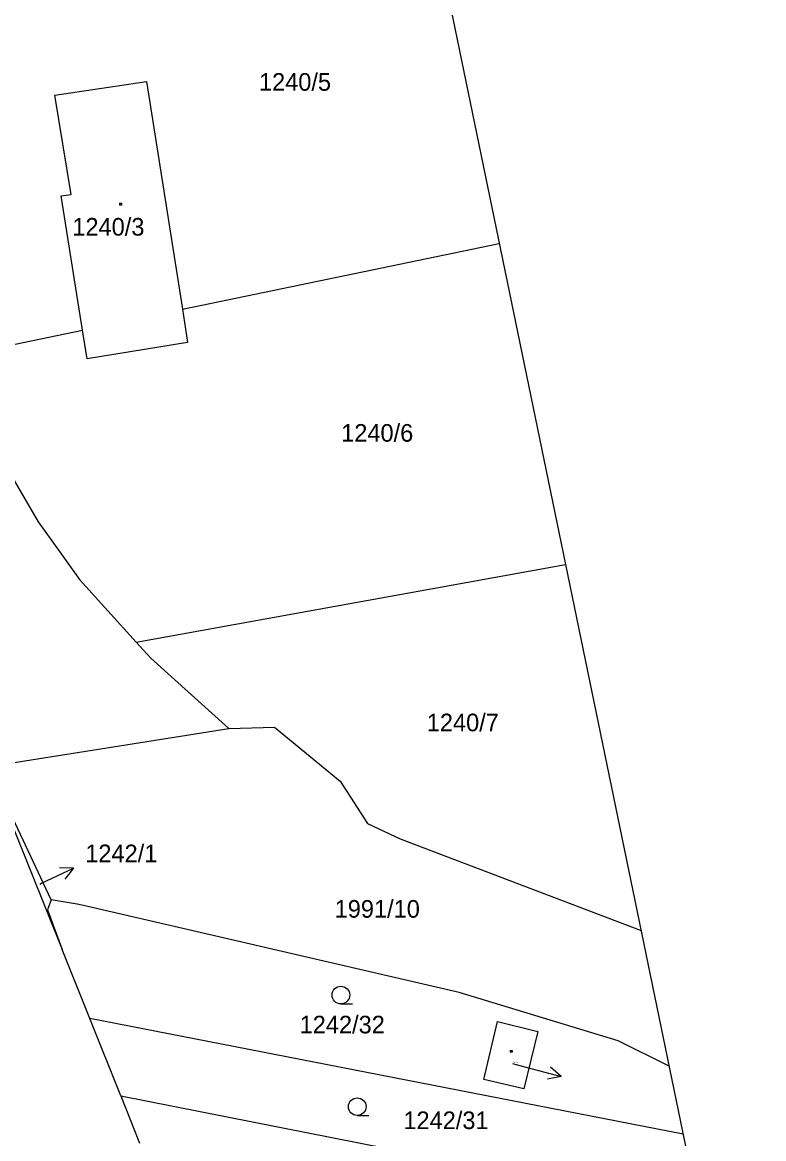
# Model space of a CAD drawing. Extents: x -804166 to -803706, y -1151030 to -1150147.
# Drawn here: x -803853.6 to -803790.5, y -1150525.9 to -1150430.9 of the extents above; entities that cross this region are included whole.
import ezdxf

# ---------------------------------------------------------------- set-up
doc = ezdxf.new("R2010")
doc.units = 0
for name, color, linetype in [('Default', 7, 'Continuous'), ('formát', 7, 'Continuous'), ('kn_celek - Cisla parcel pomocna', 7, 'Continuous'), ('kn_celek - Cisla pozemkovych parcel', 7, 'Continuous'), ('kn_celek - Cisla stavebnich parcel', 7, 'Continuous'), ('kn_celek - Hranice parcel', 7, 'Continuous'), ('kn_celek - Znacky budov', 7, 'Continuous'), ('kn_celek - Znacky kultur', 7, 'Continuous')]:
    doc.layers.add(name, color=color, linetype=linetype)

# ---------------------------------------------------------------- blocks, each defined once
blk = doc.blocks.new('304')
at = {"layer": 'Default'}
blk.add_line((-0.07, 0), (9.85, 0), dxfattribs=at)
blk.add_circle((-0.08, 7.5), 7.5, dxfattribs=at)
blk = doc.blocks.new('402')
at = {"layer": 'Default'}
for p, q in [((-0.77, 0.75), (0.73, 0.75)), ((-0.77, 0.75), (-0.77, -0.75)), ((0.73, 0.75), (0.73, -0.75)), ((0.73, -0.75), (-0.77, -0.75))]:
    blk.add_line(p, q, dxfattribs=at)
blk = doc.blocks.new('Z61')
at = {"layer": 'Default'}
for p, q in [((0, 0), (30, 0)), ((30, 0), (19.21, 5.26)), ((30, 0), (19.21, -5.26))]:
    blk.add_line(p, q, dxfattribs=at)

msp = doc.modelspace()

# ---------------------------------------------------------------- linework, layer by layer
at = {"layer": 'formát'}
msp.add_line((-803832.972, -1150353.011), (-803790.512, -1150558.674), dxfattribs=at)
at = {"layer": 'kn_celek - Cisla parcel pomocna'}
for p, q in [((-803852.112, -1150504.197), (-803851.95, -1150504.12)), ((-803811.889, -1150519.448), (-803810.63, -1150519.79))]:
    msp.add_line(p, q, dxfattribs=at)
at = {"layer": 'kn_celek - Hranice parcel'}
for p, q in [((-803850.83, -1150437.12), (-803843.02, -1150435.94)), ((-803843.02, -1150435.94), (-803839.97, -1150455.32)), ((-803849.45, -1150445.54), (-803850.83, -1150437.12)), ((-803850.28, -1150445.67), (-803849.45, -1150445.54)), ((-803848.47, -1150457.09), (-803850.28, -1150445.67)), ((-803839.97, -1150455.32), (-803813.008, -1150449.711)), ((-803839.97, -1150455.32), (-803839.53, -1150458.14)), ((-803859.37, -1150459.36), (-803848.47, -1150457.09)), ((-803848.09, -1150459.52), (-803848.47, -1150457.09)), ((-803839.53, -1150458.14), (-803848.09, -1150459.52)), ((-803855.19, -1150468.33), (-803852.25, -1150473.4)), ((-803852.25, -1150473.4), (-803850.44, -1150475.92)), ((-803850.44, -1150475.92), (-803848.74, -1150478.29)), ((-803843.91, -1150483.63), (-803807.372, -1150477.008)), ((-803848.74, -1150478.29), (-803843.91, -1150483.63)), ((-803843.91, -1150483.63), (-803842.67, -1150485)), ((-803842.67, -1150485), (-803836.01, -1150490.97)), ((-803856.47, -1150494.21), (-803836.01, -1150490.97)), ((-803836.01, -1150490.97), (-803832.13, -1150490.85)), ((-803832.13, -1150490.85), (-803826.54, -1150495.44)), ((-803851.14, -1150505.55), (-803856.47, -1150494.21)), ((-803856.47, -1150494.21), (-803850.2, -1150509.77)), ((-803826.54, -1150495.44), (-803824.23, -1150499.05)), ((-803824.23, -1150499.05), (-803821.45, -1150500.35)), ((-803821.45, -1150500.35), (-803800.942, -1150508.154)), ((-803851.14, -1150505.55), (-803851.46, -1150506.38)), ((-803848.93, -1150505.9), (-803851.14, -1150505.55)), ((-803848.39, -1150506.03), (-803848.93, -1150505.9)), ((-803816.42, -1150513.42), (-803848.39, -1150506.03)), ((-803851.46, -1150506.38), (-803850.2, -1150509.77)), ((-803847.85, -1150515.64), (-803850.2, -1150509.77)), ((-803802.9, -1150517.53), (-803816.42, -1150513.42)), ((-803845.22, -1150522.21), (-803847.85, -1150515.64)), ((-803797.366, -1150525.476), (-803847.85, -1150515.64)), ((-803814.33, -1150520.81), (-803813.17, -1150515.89)), ((-803813.17, -1150515.89), (-803809.73, -1150516.73)), ((-803809.73, -1150516.73), (-803810.93, -1150521.61)), ((-803798.563, -1150519.677), (-803802.9, -1150517.53)), ((-803810.93, -1150521.61), (-803814.33, -1150520.81)), ((-803845.22, -1150522.21), (-803843.61, -1150526.23)), ((-803845.22, -1150522.21), (-803796.041, -1150531.894))]:
    msp.add_line(p, q, dxfattribs=at)

# ---------------------------------------------------------------- block references
at = {"layer": 'kn_celek - Cisla parcel pomocna'}
for p, xscale, yscale, rotation in [((-803851.95, -1150504.12), 0.1, 0.10000000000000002, 25.354800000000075), ((-803810.63, -1150519.79), 0.09999999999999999, 0.10000000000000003, -15.196859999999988)]:
    msp.add_blockref('Z61', p, dxfattribs=dict(at, xscale=xscale, yscale=yscale, rotation=rotation))
at = {"layer": 'kn_celek - Znacky budov', "xscale": 0.1, "yscale": 0.10000000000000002}
for p in [(-803845.24, -1150446.38), (-803812, -1150518.42)]:
    msp.add_blockref('402', p, dxfattribs=at)
at = {"layer": 'kn_celek - Znacky kultur', "xscale": 0.1, "yscale": 0.10000000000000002}
for p in [(-803826.48, -1150514.39), (-803825.09, -1150523.88)]:
    msp.add_blockref('304', p, dxfattribs=at)

# ---------------------------------------------------------------- texts
at = {"layer": 'kn_celek - Cisla parcel pomocna'}
msp.add_text('1242/1', height=1.5, dxfattribs=at).set_placement((-803848.24, -1150502.34))
at = {"layer": 'kn_celek - Cisla pozemkovych parcel'}
for s, height, p in [('1240/5', 1.5, (-803833.46, -1150436.73)), ('1240/6', 1.5, (-803826.464, -1150466.58)), ('1240/7', 1.5, (-803819.179, -1150491.207)), ('1242/1', 0.1, (-803852.11, -1150504.167)), ('1991/10', 1.5, (-803827.019, -1150507.06)), ('1242/32', 1.5, (-803830, -1150516.9)), ('1242/31', 1.5, (-803821.17, -1150525.04))]:
    msp.add_text(s, height=height, dxfattribs=at).set_placement(p)
at = {"layer": 'kn_celek - Cisla stavebnich parcel'}
for s, height, p in [('1240/3', 1.5, (-803849.34, -1150449.05)), ('1242/34', 0.1, (-803811.89, -1150519.417))]:
    msp.add_text(s, height=height, dxfattribs=at).set_placement(p)

doc.saveas('drawing.dxf')
